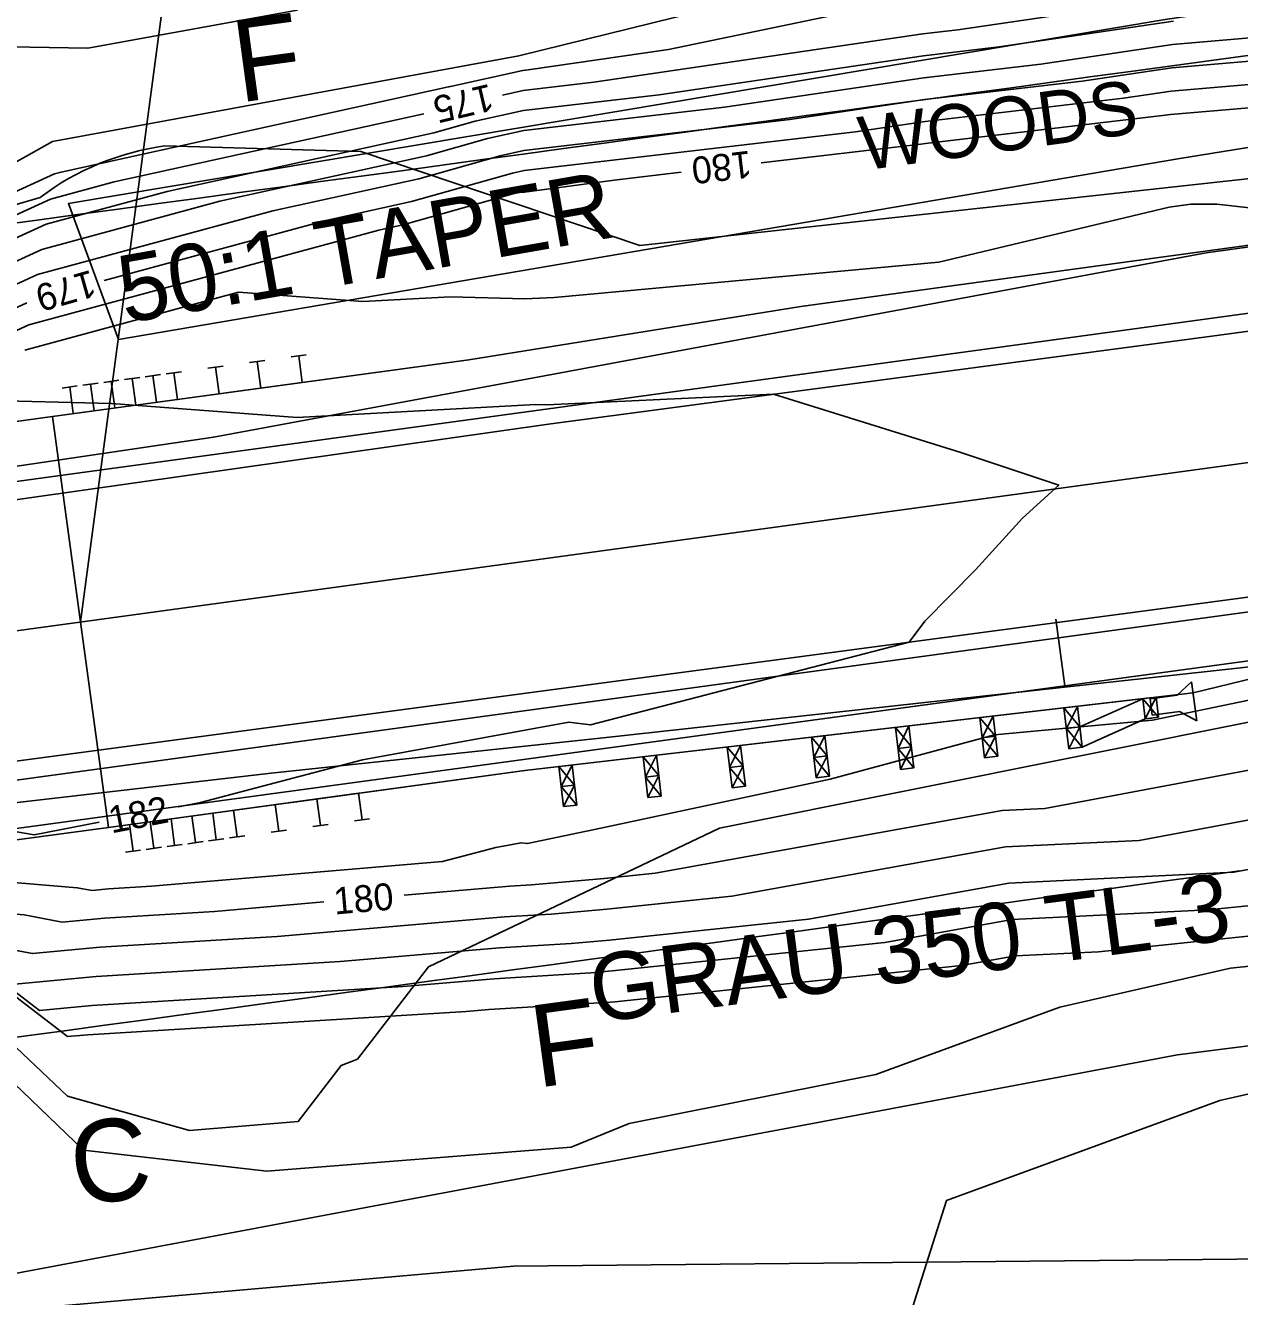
# Model space of a CAD drawing. Extents: x 2086416 to 2115205, y 575507 to 632762.
# Drawn here: x 2112116.2 to 2112206.5, y 581682.3 to 581776.8 of the extents above; entities that cross this region are included whole.
import ezdxf

# ---------------------------------------------------------------- set-up
doc = ezdxf.new("R2010")
doc.units = 0
for name, color, linetype in [('Default', 7, 'Continuous'), ('DTM Contours Major', 7, 'Continuous'), ('DTM Contours Major Text', 7, 'Continuous'), ('DTM Contours Minor', 7, 'Continuous'), ('DTM Contours Minor Text', 7, 'Continuous'), ('Exist Guardrail', 7, 'Continuous'), ('Exist Hydro Stream or Body of Water', 7, 'Continuous'), ('Exist Hydrographic FEMA Cross Section', 7, 'Continuous'), ('Exist Right of Way Line', 7, 'Continuous'), ('Exist Roads EOP', 7, 'Continuous'), ('Exist Vegetation Woods Line', 7, 'Continuous'), ('Exist Vegetation Woods Line Text', 7, 'Continuous'), ('Prop Horizontal Alignment', 7, 'Continuous'), ('Prop Horizontal Alignment Station Label', 7, 'Continuous'), ('Prop Roadway Bridge', 7, 'Continuous'), ('Prop SS Cut Line', 7, 'Continuous'), ('Prop SS Cut Text', 7, 'Continuous'), ('Prop SS Fill Line', 7, 'Continuous'), ('Prop SS Fill Text', 7, 'Continuous')]:
    doc.layers.add(name, color=color, linetype=linetype)

msp = doc.modelspace()

# ---------------------------------------------------------------- linework, layer by layer
at = {"layer": 'Default'}
for p, q in [((2112048.04, 581707.887), (2112618.339, 581785.483)), ((2112173.877, 581755.881), (2112283.513, 581770.843)), ((2112283.513, 581770.843), (2112173.877, 581755.881)), ((2111430.061, 581649.328), (2112312.029, 581769.688)), ((2112149.186, 581751.922), (2112173.877, 581755.881)), ((2112173.877, 581755.881), (2112149.186, 581751.922)), ((2112149.186, 581751.922), (2112118.223, 581747.697)), ((2112149.186, 581751.922), (2112131.313, 581749.483)), ((2112132.866, 581751.714), (2112134.001, 581751.869)), ((2112133.704, 581749.81), (2112133.434, 581751.791)), ((2112135.963, 581752.136), (2112137.097, 581752.291)), ((2112136.8, 581750.232), (2112136.53, 581752.214)), ((2112125.125, 581750.657), (2112126.26, 581750.812)), ((2112126.674, 581750.869), (2112127.809, 581751.024)), ((2112127.512, 581748.965), (2112127.241, 581750.946)), ((2112129.77, 581751.291), (2112130.905, 581751.446)), ((2112130.608, 581749.387), (2112130.337, 581751.369)), ((2112118.223, 581747.697), (2112136.8, 581750.232)), ((2112118.933, 581749.812), (2112120.068, 581749.967)), ((2112119.771, 581747.908), (2112119.5, 581749.89)), ((2112120.481, 581750.024), (2112121.616, 581750.179)), ((2112121.319, 581748.119), (2112121.049, 581750.101)), ((2112122.029, 581750.235), (2112123.164, 581750.39)), ((2112122.867, 581748.331), (2112122.597, 581750.312)), ((2112123.577, 581750.446), (2112124.712, 581750.601)), ((2112124.415, 581748.542), (2112124.145, 581750.524)), ((2112125.963, 581748.753), (2112125.693, 581750.735)), ((2111433.036, 581627.53), (2112315.004, 581747.89)), ((2112203.031, 581727.142), (2112234.275, 581734.854)), ((2112193.505, 581727.679), (2112192.831, 581732.634)), ((2112153.355, 581721.372), (2112203.031, 581727.142)), ((2112201.863, 581726.968), (2112202.913, 581727.978)), ((2112202.913, 581727.978), (2112203.307, 581725.065)), ((2112153.355, 581721.372), (2112199.794, 581726.766)), ((2112194.606, 581724.621), (2112199.297, 581726.708)), ((2112199.297, 581726.708), (2112199.47, 581725.218)), ((2112200.464, 581725.334), (2112199.297, 581726.708)), ((2112200.29, 581726.824), (2112199.47, 581725.218)), ((2112199.835, 581726.695), (2112201.863, 581726.968)), ((2112199.915, 581726.089), (2112199.835, 581726.695)), ((2112200.29, 581726.824), (2112200.464, 581725.334)), ((2112187.176, 581725.301), (2112187.522, 581722.321)), ((2112187.176, 581725.301), (2112188.343, 581723.926)), ((2112187.349, 581723.81), (2112188.17, 581725.416)), ((2112188.17, 581725.416), (2112188.516, 581722.436)), ((2112193.435, 581726.028), (2112193.789, 581722.984)), ((2112193.435, 581726.028), (2112194.606, 581724.621)), ((2112193.613, 581724.506), (2112194.429, 581726.143)), ((2112194.429, 581726.143), (2112194.782, 581723.1)), ((2112199.47, 581725.218), (2112200.464, 581725.334)), ((2112199.47, 581725.218), (2112199.967, 581725.276)), ((2112199.996, 581725.484), (2112199.915, 581726.089)), ((2112202.025, 581725.757), (2112199.996, 581725.484)), ((2112203.307, 581725.065), (2112202.025, 581725.757)), ((2112180.917, 581724.574), (2112181.279, 581721.457)), ((2112180.917, 581724.574), (2112182.091, 581723.131)), ((2112181.097, 581723.016), (2112181.91, 581724.689)), ((2112181.91, 581724.689), (2112182.272, 581721.572)), ((2112193.613, 581724.506), (2112194.606, 581724.621)), ((2112194.782, 581723.1), (2112193.613, 581724.506)), ((2112194.606, 581724.621), (2112193.789, 581722.984)), ((2112194.782, 581723.1), (2112199.47, 581725.218)), ((2112174.658, 581723.847), (2112175.651, 581723.962)), ((2112174.658, 581723.847), (2112175.008, 581720.831)), ((2112174.658, 581723.847), (2112175.827, 581722.454)), ((2112174.833, 581722.338), (2112175.651, 581723.962)), ((2112175.651, 581723.962), (2112176.001, 581720.947)), ((2112187.349, 581723.81), (2112188.343, 581723.926)), ((2112188.516, 581722.436), (2112187.349, 581723.81)), ((2112188.343, 581723.926), (2112187.522, 581722.321)), ((2112162.316, 581720.877), (2112163.133, 581722.508)), ((2112163.133, 581722.508), (2112163.485, 581719.476)), ((2112168.399, 581723.12), (2112168.75, 581720.092)), ((2112168.399, 581723.12), (2112169.568, 581721.721)), ((2112168.575, 581721.606), (2112169.392, 581723.235)), ((2112169.392, 581723.235), (2112169.744, 581720.208)), ((2112174.833, 581722.338), (2112175.827, 581722.454)), ((2112175.827, 581722.454), (2112175.008, 581720.831)), ((2112181.097, 581723.016), (2112182.091, 581723.131)), ((2112182.272, 581721.572), (2112181.097, 581723.016)), ((2112182.091, 581723.131), (2112181.279, 581721.457)), ((2112187.522, 581722.321), (2112188.516, 581722.436)), ((2112193.789, 581722.984), (2112194.782, 581723.1)), ((2112155.88, 581721.666), (2112156.874, 581721.781)), ((2112155.88, 581721.666), (2112156.226, 581718.686)), ((2112157.047, 581720.291), (2112155.88, 581721.666)), ((2112156.053, 581720.175), (2112156.874, 581721.781)), ((2112156.874, 581721.781), (2112157.22, 581718.801)), ((2112156.874, 581721.781), (2112157.047, 581720.291)), ((2112162.139, 581722.393), (2112162.492, 581719.36)), ((2112162.139, 581722.393), (2112163.309, 581720.992)), ((2112168.575, 581721.606), (2112169.568, 581721.721)), ((2112169.744, 581720.208), (2112168.575, 581721.606)), ((2112169.568, 581721.721), (2112168.75, 581720.092)), ((2112176.001, 581720.947), (2112174.833, 581722.338)), ((2112181.279, 581721.457), (2112182.272, 581721.572)), ((2112122.392, 581717.147), (2112153.355, 581721.372)), ((2112136.015, 581719.006), (2112153.355, 581721.372)), ((2112162.316, 581720.877), (2112163.309, 581720.992)), ((2112163.485, 581719.476), (2112162.316, 581720.877)), ((2112163.309, 581720.992), (2112162.492, 581719.36)), ((2112175.008, 581720.831), (2112176.001, 581720.947)), ((2112122.392, 581717.147), (2112140.97, 581719.682)), ((2112140.97, 581719.682), (2112141.24, 581717.7)), ((2112156.053, 581720.175), (2112157.047, 581720.291)), ((2112157.22, 581718.801), (2112156.053, 581720.175)), ((2112157.047, 581720.291), (2112156.226, 581718.686)), ((2112168.75, 581720.092), (2112169.744, 581720.208)), ((2112134.777, 581718.837), (2112135.047, 581716.855)), ((2112137.873, 581719.26), (2112138.144, 581717.278)), ((2112156.226, 581718.686), (2112157.22, 581718.801)), ((2112162.492, 581719.36), (2112163.485, 581719.476)), ((2112127.036, 581717.781), (2112127.307, 581715.799)), ((2112128.584, 581717.992), (2112128.855, 581716.01)), ((2112130.133, 581718.203), (2112130.403, 581716.222)), ((2112131.681, 581718.414), (2112131.951, 581716.433)), ((2112140.672, 581717.623), (2112141.807, 581717.778)), ((2112123.94, 581717.358), (2112124.21, 581715.376)), ((2112125.488, 581717.569), (2112125.758, 581715.588)), ((2112134.48, 581716.778), (2112135.615, 581716.933)), ((2112137.576, 581717.2), (2112138.711, 581717.355)), ((2112126.739, 581715.722), (2112127.874, 581715.876)), ((2112128.287, 581715.933), (2112129.422, 581716.088)), ((2112129.835, 581716.144), (2112130.97, 581716.299)), ((2112131.384, 581716.355), (2112132.519, 581716.51)), ((2112123.643, 581715.299), (2112124.778, 581715.454)), ((2112125.191, 581715.51), (2112126.326, 581715.665))]:
    msp.add_line(p, q, dxfattribs=at)
at = {"layer": 'DTM Contours Major'}
for points in [[(2112250.839, 581784.309), (2112248.782, 581784.045), (2112244.237, 581783.676), (2112231.316, 581782.168), (2112205.508, 581779.154), (2112201.621, 581778.822), (2112185.538, 581776.447), (2112182.95, 581776.143), (2112158.467, 581772.545), (2112153.211, 581771.929), (2112151.675, 581771.592)], [(2112170.922, 581766.56), (2112182.787, 581767.949), (2112183.139, 581768.001), (2112200.95, 581770.095), (2112201.361, 581770.156), (2112209.825, 581770.879), (2112224.625, 581770.841), (2112231.702, 581770.049), (2112241.358, 581771.638), (2112251.989, 581771.894), (2112261.138, 581772.97), (2112270.401, 581772.136)], [(2112145.839, 581770.21), (2112122.802, 581765.151), (2112118.062, 581763.867), (2112111.066, 581760.66)], [(2112107.271, 581718.408), (2112107.011, 581720.415), (2112104.169, 581741.708), (2112103.667, 581744.929), (2112103.375, 581747.122), (2112103.578, 581747.166), (2112103.753, 581747.19), (2112103.841, 581746.714), (2112104.339, 581748.104), (2112105.63, 581751.758), (2112105.895, 581751.758), (2112105.958, 581751.161), (2112105.765, 581750.292), (2112105.481, 581749.341), (2112113.377, 581753.212), (2112114.641, 581753.669), (2112116.475, 581754.51), (2112142.486, 581761.555), (2112144.37, 581761.969), (2112152.892, 581764.375), (2112153.328, 581764.365), (2112159.99, 581765.28), (2112164.963, 581765.862)], [(2112243.264, 581724.608), (2112242.636, 581724.477), (2112237.314, 581722.948), (2112235.596, 581722.341), (2112231.268, 581722.095), (2112207.567, 581721.477), (2112192.009, 581718.555), (2112188.848, 581718.404), (2112163.044, 581713.742), (2112159.246, 581713.344), (2112153.837, 581712.875), (2112152.233, 581712.778), (2112144.377, 581712.107)], [(2112138.399, 581711.597), (2112130.259, 581710.902), (2112122.081, 581710.4), (2112118.952, 581710.106), (2112116.105, 581710.634), (2112111.62, 581711.009), (2112111.602, 581710.95), (2112111.782, 581710.545), (2112111.856, 581710.027), (2112111.763, 581709.651), (2112108.131, 581715.026), (2112108.22, 581714.185), (2112108.051, 581714.162), (2112107.834, 581714.227), (2112107.82, 581714.32), (2112107.547, 581716.398), (2112107.271, 581718.408)], [(2112115.349, 581698.132), (2112120.526, 581693.141), (2112134.165, 581691.587), (2112156.789, 581693.375), (2112161.111, 581695.134), (2112179.456, 581698.777), (2112193.131, 581703.787), (2112205.816, 581706.664), (2112209.412, 581707.038), (2112211.228, 581707.28)]]:
    msp.add_lwpolyline(points, dxfattribs=at)
at = {"layer": 'DTM Contours Minor'}
for points in [[(2112307.142, 581785.738), (2112301.4, 581785.104), (2112285.905, 581782.951), (2112280.275, 581782.232), (2112257.984, 581779.142), (2112250.535, 581778.186), (2112235.839, 581776.992), (2112231.218, 581776.453), (2112221.989, 581775.375), (2112201.465, 581773.622), (2112194.785, 581772.636), (2112183.064, 581771.258), (2112173.059, 581769.787), (2112153.283, 581767.472), (2112151.503, 581767.081), (2112145.472, 581765.379), (2112134.612, 581762.993), (2112117.11, 581758.253), (2112113.211, 581756.465), (2112110.524, 581755.494), (2112110.041, 581755.257)], [(2112217.816, 581784.761), (2112201.188, 581783.128), (2112192.056, 581780.852), (2112182.632, 581778.883), (2112164.02, 581774.995), (2112153.603, 581773.464), (2112153.187, 581773.415), (2112147.809, 581772.235), (2112147.676, 581772.198), (2112118.865, 581765.87), (2112118.38, 581765.739), (2112114.812, 581764.103), (2112110.366, 581762.541), (2112109.222, 581761.56), (2112106.527, 581760.029), (2112104.587, 581757.383), (2112103.763, 581755.943), (2112103.404, 581754.716)], [(2112319.856, 581781.597), (2112316.737, 581781.967), (2112303.887, 581783.453), (2112301.358, 581783.173), (2112281.8, 581780.456), (2112280.881, 581780.338), (2112253.083, 581776.485), (2112251.12, 581776.233), (2112233.04, 581774.765), (2112231.186, 581774.548), (2112227.483, 581774.116), (2112201.413, 581771.889), (2112197.868, 581771.366), (2112183.101, 581769.629), (2112177.923, 581768.868), (2112153.307, 581765.986), (2112152.426, 581765.792), (2112144.921, 581763.674), (2112138.549, 581762.274), (2112122.072, 581757.811)], [(2112139.56, 581778.479), (2112120.846, 581775.075), (2112115.093, 581775.188), (2112112.213, 581774.86), (2112110.474, 581776.28), (2112108.396, 581772.246), (2112107.475, 581779.066)], [(2112201.569, 581777.089), (2112188.62, 581775.177), (2112182.988, 581774.514), (2112163.331, 581771.626), (2112153.235, 581770.443), (2112149.656, 581769.658), (2112146.574, 581768.788), (2112126.738, 581764.432), (2112117.745, 581761.996), (2112111.781, 581759.262)], [(2112216.496, 581776.635), (2112201.517, 581775.356), (2112191.703, 581773.906), (2112183.026, 581772.886), (2112168.195, 581770.707), (2112153.259, 581768.958), (2112150.579, 581768.369), (2112146.023, 581767.083), (2112130.675, 581763.713), (2112117.427, 581760.124), (2112112.496, 581757.864)], [(2112116.157, 581752.638), (2112132.065, 581756.947), (2112141.305, 581756.248), (2112147.816, 581756.602), (2112153.344, 581756.447), (2112155.536, 581756.549), (2112184.118, 581759.163), (2112201.268, 581763.261), (2112202.871, 581763.48), (2112204.811, 581763.475), (2112233.332, 581760.281)], [(2112116.311, 581756.16), (2112113.926, 581755.067)], [(2112112.703, 581748.9), (2112122.622, 581748.662), (2112136.42, 581747.618), (2112154.155, 581748.582), (2112154.99, 581748.559), (2112171.825, 581749.346), (2112185.777, 581745.024), (2112193.045, 581742.592), (2112190.36, 581740.14), (2112186.857, 581736.306), (2112183.084, 581732.472), (2112181.933, 581730.911), (2112158.22, 581724.776), (2112156.617, 581724.968), (2112141.274, 581722.172), (2112129.236, 581718.999), (2112127.589, 581718.679)], [(2112111.792, 581709.149), (2112114.444, 581705.224), (2112114.542, 581705.292), (2112119.327, 581701.586), (2112120.838, 581701.727), (2112148.974, 581703.457), (2112150.668, 581703.601), (2112159.721, 581704.147), (2112160.026, 581704.174), (2112185.809, 581706.879), (2112189.823, 581707.604), (2112196.012, 581707.9), (2112209.237, 581709.275), (2112223.325, 581711.149), (2112238.713, 581713.223), (2112245.11, 581713.27), (2112258.687, 581714.946), (2112279.049, 581720.19), (2112287.683, 581722.509), (2112302.257, 581726.24), (2112306.106, 581727.279)], [(2112207.184, 581726.594), (2112200.011, 581725.127), (2112188.26, 581724.028), (2112176.048, 581720.731), (2112158.984, 581717.087), (2112153.547, 581715.942), (2112153.064, 581716), (2112151.191, 581715.658), (2112147.214, 581714.61), (2112125.581, 581712.764), (2112122.392, 581712.568), (2112121.172, 581712.453), (2112120.062, 581712.659), (2112110.053, 581713.496)], [(2112106.842, 581721.299), (2112107.146, 581719.085), (2112107.76, 581714.411), (2112107.792, 581714.203), (2112108.279, 581714.058), (2112108.349, 581714.067), (2112108.312, 581714.413), (2112112.124, 581708.773), (2112114.44, 581705.345), (2112114.687, 581705.516), (2112117.252, 581703.53), (2112121.149, 581703.895), (2112144.296, 581705.318), (2112151.059, 581705.895), (2112158.25, 581706.329), (2112159.831, 581706.466), (2112180.117, 581708.595), (2112189.579, 581710.304), (2112204.165, 581711.003), (2112209.062, 581711.512)], [(2112121.699, 581717.534), (2112116.85, 581716.592), (2112108.635, 581718.001), (2112108.639, 581717.019), (2112108.444, 581715.847), (2112108.423, 581715.779), (2112108.452, 581715.715), (2112108.605, 581714.636), (2112108.59, 581714.576), (2112108.01, 581715.434), (2112108.133, 581714.263), (2112107.899, 581714.232), (2112107.862, 581714.243), (2112107.86, 581714.258), (2112107.814, 581714.607), (2112107.768, 581714.944)], [(2112113.249, 581708.405), (2112116.731, 581707.758), (2112121.771, 581708.232), (2112134.938, 581709.041), (2112151.842, 581710.484), (2112155.308, 581710.693), (2112159.441, 581711.051), (2112168.735, 581712.026), (2112189.092, 581715.704), (2112199.036, 581716.18), (2112208.144, 581717.89)], [(2112115.177, 581705.474), (2112121.46, 581706.063), (2112139.617, 581707.179), (2112151.45, 581708.189), (2112156.779, 581708.511), (2112159.636, 581708.759), (2112174.426, 581710.31), (2112189.335, 581713.004), (2112206.064, 581713.805), (2112208.721, 581714.304)], [(2112232.328, 581703.336), (2112232.243, 581704.795), (2112211.345, 581698.276), (2112205.023, 581696.842), (2112184.696, 581689.394), (2112179.326, 581672.479), (2112183.707, 581663.85), (2112184.184, 581659.926), (2112183.356, 581652.629), (2112202.937, 581641.218), (2112233.957, 581631.143), (2112236.481, 581627.862), (2112240.002, 581631.414), (2112272.917, 581654.121), (2112271.451, 581659.305)]]:
    msp.add_lwpolyline(points, dxfattribs=at)
at = {"layer": 'Exist Guardrail'}
for points in [[(2112105.471, 581742.51), (2112130.199, 581746.155), (2112154.81, 581750.731), (2112204.013, 581759.862), (2112253.579, 581766.728), (2112303.016, 581773.358), (2112346.602, 581779.364), (2112403.93, 581787.617)], [(2112259.946, 581734.593), (2112208.584, 581729.222), (2112158.945, 581723.773), (2112134.486, 581721.17), (2112109.385, 581718.283)]]:
    msp.add_lwpolyline(points, dxfattribs=at)
at = {"layer": 'Exist Hydro Stream or Body of Water'}
msp.add_lwpolyline([(2112100.331, 581748.533), (2112103.118, 581756.422), (2112105.733, 581760.694), (2112110.228, 581763.659), (2112118.219, 581768.137), (2112152.909, 581774.525), (2112200.706, 581786.301), (2112247.28, 581789.733), (2112301.109, 581801.74), (2112342.553, 581803.718), (2112346.945, 581801.461), (2112350.791, 581799.078), (2112399.711, 581802.75), (2112440.348, 581810.488), (2112440.68, 581811.969), (2112437.892, 581820.198), (2112440.302, 581822.201), (2112435.858, 581828.249), (2112435.37, 581831.558), (2112437.975, 581841.005), (2112494.538, 581874.355), (2112499.44, 581880.388)], dxfattribs=at)
at = {"layer": 'Exist Hydrographic FEMA Cross Section'}
msp.add_lwpolyline([(2112356.495, 581719.738), (2112346.578, 581718.488), (2112341.62, 581717.863), (2112336.656, 581717.238), (2112326.74, 581715.988), (2112316.823, 581714.732), (2112306.906, 581713.482), (2112296.99, 581712.232), (2112287.073, 581710.977), (2112277.156, 581709.727), (2112267.239, 581708.477), (2112257.323, 581707.222), (2112247.406, 581705.972), (2112237.489, 581704.722), (2112227.573, 581703.467), (2112217.656, 581702.217), (2112207.74, 581700.967), (2112201.875, 581700.225), (2111922.666, 581647.707)], dxfattribs=at)
at = {"layer": 'Exist Right of Way Line'}
msp.add_lwpolyline([(2112198.38, 581773.354), (2112400.409, 581800.925)], dxfattribs=at)
for radius in [86637.248, 86697.248]:
    msp.add_arc((2100483.795, 667614.96), radius, 277.64238767, 277.77100557, dxfattribs=at)
at = {"layer": 'Exist Roads EOP'}
for points in [[(2112106.042, 581730.564), (2112104.785, 581739.983), (2112155.283, 581747.155), (2112204.047, 581753.613), (2112253.47, 581760.299), (2112302.941, 581766.962), (2112352.114, 581773.791), (2112401.717, 581780.294), (2112450.223, 581786.9), (2112499.859, 581793.893), (2112548.734, 581800.819), (2112597.587, 581807.574), (2112647.293, 581814.654)], [(2112106.042, 581730.564), (2112107.323, 581720.971), (2112157.697, 581727.695), (2112206.747, 581734.204), (2112256.301, 581741.075), (2112305.324, 581747.934), (2112354.53, 581754.867), (2112403.988, 581761.609), (2112453.008, 581768.182), (2112502.287, 581774.875), (2112551.211, 581782.051), (2112600.406, 581788.813), (2112649.895, 581795.881)]]:
    msp.add_lwpolyline(points, dxfattribs=at)
at = {"layer": 'Exist Vegetation Woods Line'}
for points in [[(2112301.36, 581782.951), (2112202.062, 581766.89), (2112123.133, 581753.422), (2112119.41, 581763.532), (2112200.966, 581777.217), (2112301.435, 581791.882), (2112399.2, 581802.758), (2112436.699, 581809.606), (2112455.709, 581861.801)], [(2112111.955, 581666.924), (2112111.49, 581680.936), (2112152.501, 581684.529), (2112262.631, 581685.586), (2112360.384, 581709.416), (2112461.663, 581723.724), (2112531.13, 581752.365)]]:
    msp.add_lwpolyline(points, dxfattribs=at)
at = {"layer": 'Prop Horizontal Alignment'}
msp.add_line((2111431.548, 581638.429), (2112404.465, 581771.2), dxfattribs=at)
at = {"layer": 'Prop Horizontal Alignment Station Label'}
msp.add_line((2112120.307, 581732.422), (2112135.809, 581848.952), dxfattribs=at)
at = {"layer": 'Prop Roadway Bridge'}
for p, q in [((2112118.223, 581747.697), (2112038.957, 581736.88)), ((2112122.392, 581717.147), (2112118.223, 581747.697)), ((2112043.126, 581706.33), (2112122.392, 581717.147))]:
    msp.add_line(p, q, dxfattribs=at)
at = {"layer": 'Prop SS Cut Line'}
for p, q in [((2112115.106, 581763.341), (2112117.304, 581763.989)), ((2112111.36, 581704.719), (2112119.344, 581697.161))]:
    msp.add_line(p, q, dxfattribs=at)
msp.add_lwpolyline([(2112119.344, 581697.161), (2112128.422, 581694.599), (2112136.48, 581695.267)], dxfattribs=at)
at = {"layer": 'Prop SS Fill Line'}
for p, q in [((2112141.145, 581767.399), (2112126.579, 581767.813)), ((2112141.145, 581767.399), (2112161.906, 581760.405)), ((2112161.906, 581760.405), (2112211.623, 581765.873)), ((2112167.819, 581717.075), (2112216.939, 581726.918)), ((2112146.186, 581706.777), (2112167.819, 581717.075))]:
    msp.add_line(p, q, dxfattribs=at)
msp.add_lwpolyline([(2112146.186, 581706.777), (2112140.893, 581699.907), (2112139.687, 581699.444), (2112136.48, 581695.267)], dxfattribs=at)
msp.add_arc((2112129.24, 581748.197), 19.795, 97.72442, 127.08439, dxfattribs=at)

# ---------------------------------------------------------------- texts
at = {"layer": 'Default'}
for s, rotation, p in [('50:1 TAPER', 9.99628, (2112123.602, 581754.612)), ('GRAU 350 TL-3', 7.47611, (2112158.511, 581702.595))]:
    msp.add_text(s, height=5, rotation=rotation, dxfattribs=at).set_placement(p)
at = {"layer": 'DTM Contours Major Text'}
for s, rotation, p in [('175', 193.32209, (2112150.729, 581772.447)), ('180', 186.67883, (2112170.086, 581767.469)), ('180', 4.87863, (2112139.206, 581710.662))]:
    msp.add_text(s, height=2, rotation=rotation, dxfattribs=at).set_placement(p)
at = {"layer": 'DTM Contours Minor Text'}
for s, rotation, p in [('179', 195.98907, (2112121.089, 581758.615)), ('182', 10.99761, (2112122.601, 581716.691))]:
    msp.add_text(s, height=2, rotation=rotation, dxfattribs=at).set_placement(p)
at = {"layer": 'Exist Vegetation Woods Line Text'}
msp.add_text('WOODS', height=4, rotation=7.77101, dxfattribs=at).set_placement((2112178.496, 581765.981))
at = {"layer": 'Prop SS Cut Text'}
msp.add_text('C', height=6.104, rotation=7.77101, dxfattribs=at).set_placement((2112119.984, 581688.962))
at = {"layer": 'Prop SS Fill Text'}
for p in [(2112132.107, 581771.034), (2112154.261, 581697.78)]:
    msp.add_text('F', height=6.104, rotation=7.77101, dxfattribs=at).set_placement(p)

doc.saveas('drawing.dxf')
